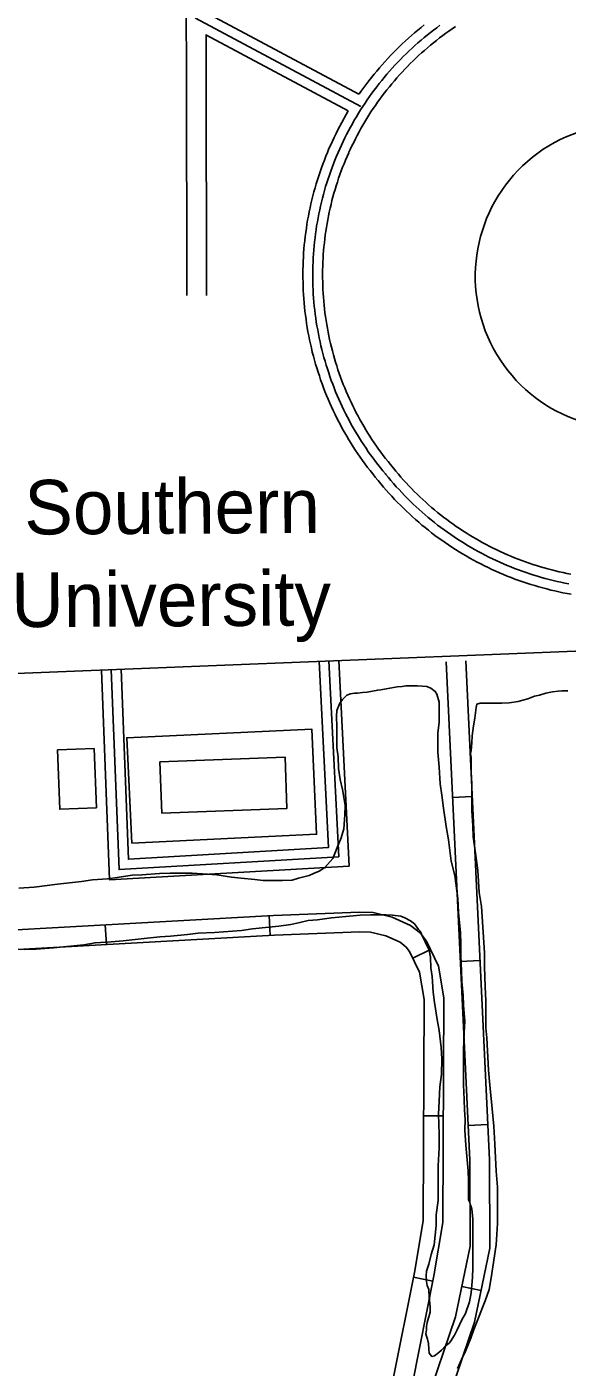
# Model space of a CAD drawing. Extents: x 3313442 to 3351311, y 721974 to 747360.
# Drawn here: x 3326444 to 3327267, y 733684 to 735725 of the extents above; entities that cross this region are included whole.
import ezdxf

# ---------------------------------------------------------------- set-up
doc = ezdxf.new("R2010")
doc.units = 0
for name, color, linetype in [('V-BLDG-IDEN', 7, 'Continuous'), ('V-BLDG-OTLN', 7, 'Continuous'), ('V-ROAD-CNTR', 7, 'Continuous'), ('V-SITE-VEGE', 7, 'Continuous')]:
    doc.layers.add(name, color=color, linetype=linetype)

msp = doc.modelspace()

# ---------------------------------------------------------------- linework, layer by layer
at = {"layer": 'V-BLDG-OTLN'}
for points in [[(3326603.5, 734482.5), (3326595.9, 734642.8), (3326877.7, 734656.1), (3326885.3, 734495.9)], [(3326490.3, 734624.2), (3326546.2, 734626.4), (3326549.7, 734536.1), (3326493.8, 734534)], [(3326649.6, 734527.8), (3326646.6, 734605.9), (3326837.1, 734613.3), (3326840.1, 734535.2)], [(3326649.6, 734527.8), (3326840.1, 734535.2), (3326837.1, 734613.3), (3326646.6, 734605.9)]]:
    msp.add_lwpolyline(points, close=True, dxfattribs=at)
at = {"layer": 'V-ROAD-CNTR'}
for p, q in [((3327092.3, 734551.7), (3327122.3, 734553.1)), ((3326812.9, 734371.9), (3326814.6, 734341.9)), ((3326563.3, 734357.8), (3326564.9, 734327.9)), ((3327058.6, 734320.2), (3327031.6, 734307.2)), ((3327104.2, 734301.9), (3327134.2, 734303.4)), ((3327078.4, 734066.9), (3327048.4, 734067.1)), ((3327116.1, 734052.2), (3327146.1, 734053.7)), ((3327062.3, 733815.5), (3327032.8, 733821.4)), ((3327106.5, 733807.4), (3327135.9, 733801.3))]:
    msp.add_line(p, q, dxfattribs=at)
for points in [[(3326952.7, 735604), (3326700.7, 735738.5), (3326692.7, 735930.9)], [(3326949.5, 735622.7), (3326715.3, 735747.7), (3326708.3, 735916.3)], [(3326686.4, 735744.1), (3326687.2, 735662.7), (3326687.3, 735316.1)], [(3326933.5, 735597.2), (3326716.6, 735713)], [(3326716.7, 735713.7), (3326717.2, 735662.9), (3326717.3, 735316.1)], [(3326920.4, 735539.4), (3326922.9, 735545), (3326925.5, 735550.6), (3326928.2, 735556.1), (3326931, 735561.5), (3326933.8, 735567), (3326936.7, 735572.4), (3326939.7, 735577.7), (3326942.7, 735583.1), (3326945.8, 735588.3), (3326949, 735593.6), (3326952.3, 735598.8), (3326955.6, 735603.9), (3326959, 735609), (3326962.4, 735614.1), (3326965.9, 735619.1), (3326969.5, 735624.1), (3326973.1, 735629), (3326976.9, 735633.9), (3326980.6, 735638.8), (3326984.5, 735643.5), (3326988.4, 735648.3), (3326992.3, 735653), (3326996.3, 735657.6), (3327000.4, 735662.2), (3327004.5, 735666.7), (3327008.7, 735671.1), (3327013, 735675.6), (3327017.3, 735679.9), (3327021.7, 735684.2), (3327026.1, 735688.5), (3327030.6, 735692.6), (3327035.1, 735696.8), (3327039.7, 735700.8), (3327044.3, 735704.8), (3327049, 735708.8), (3327053.8, 735712.7), (3327058.6, 735716.5), (3327063.4, 735720.3), (3327068.3, 735723.9), (3327073.2, 735727.6)], [(3326934, 735533.2), (3326936.5, 735538.7), (3326939.1, 735544.1), (3326941.7, 735549.4), (3326944.3, 735554.7), (3326947.1, 735560), (3326949.9, 735565.2), (3326952.8, 735570.4), (3326955.7, 735575.5), (3326958.7, 735580.6), (3326961.8, 735585.7), (3326964.9, 735590.8), (3326968.1, 735595.7), (3326971.4, 735600.7), (3326974.8, 735605.6), (3326978.2, 735610.5), (3326981.6, 735615.3), (3326985.1, 735620), (3326988.7, 735624.8), (3326992.4, 735629.5), (3326996.1, 735634.1), (3326999.9, 735638.7), (3327003.7, 735643.2), (3327007.6, 735647.7), (3327011.5, 735652.1), (3327015.5, 735656.5), (3327019.6, 735660.8), (3327023.7, 735665.1), (3327027.9, 735669.3), (3327032.1, 735673.5), (3327036.4, 735677.6), (3327040.7, 735681.6), (3327045.1, 735685.6), (3327049.6, 735689.5), (3327054.1, 735693.4), (3327058.6, 735697.2), (3327063.2, 735701), (3327067.8, 735704.7), (3327072.5, 735708.3), (3327077.3, 735711.9), (3327082, 735715.4), (3327086.9, 735718.9), (3327091.7, 735722.3), (3327096.6, 735725.6)], [(3326949.5, 735622.7), (3326965, 735643.1), (3326968.9, 735648.1), (3326972.8, 735653), (3326976.8, 735657.9), (3326980.9, 735662.7), (3326985.1, 735667.5), (3326989.3, 735672.2), (3326993.5, 735676.9), (3326997.9, 735681.5), (3327002.3, 735686), (3327006.7, 735690.5), (3327011.2, 735695), (3327015.8, 735699.4), (3327020.4, 735703.7), (3327025.1, 735707.9), (3327029.8, 735712.1), (3327034.6, 735716.3), (3327039.4, 735720.3), (3327044.3, 735724.3), (3327049.3, 735728.3)], [(3326951.2, 735624.2), (3326952.7, 735626.4)], [(3326906.7, 735545.7), (3326909.3, 735551.3), (3326912, 735557), (3326914.8, 735562.7), (3326917.6, 735568.4), (3326920.6, 735574), (3326933.2, 735597.4)], [(3326978.6, 735034.8), (3326974.6, 735039.6), (3326970.7, 735044.5), (3326966.7, 735049.5), (3326962.9, 735054.5), (3326959.1, 735059.6), (3326955.4, 735064.7), (3326951.7, 735069.8), (3326948.1, 735075.1), (3326944.6, 735080.3), (3326941.1, 735085.6), (3326937.8, 735091), (3326934.5, 735096.3), (3326931.2, 735101.8), (3326928, 735107.2), (3326924.9, 735112.8), (3326921.9, 735118.3), (3326919, 735123.9), (3326916.1, 735129.5), (3326913.3, 735135.2), (3326910.5, 735140.9), (3326907.9, 735146.6), (3326905.3, 735152.4), (3326902.8, 735158.2), (3326900.4, 735164.1), (3326898, 735169.9), (3326895.7, 735175.8), (3326893.5, 735181.8), (3326891.4, 735187.7), (3326889.4, 735193.7), (3326887.4, 735199.7), (3326885.5, 735205.8), (3326883.7, 735211.8), (3326882, 735217.9), (3326880.3, 735224), (3326878.7, 735230.1), (3326877.3, 735236.3), (3326875.8, 735242.5), (3326874.5, 735248.6), (3326873.3, 735254.8), (3326872.1, 735261.1), (3326871, 735267.3), (3326870, 735273.5), (3326869.1, 735279.8), (3326868.2, 735286.1), (3326867.5, 735292.3), (3326866.8, 735298.6), (3326866.2, 735304.9), (3326865.7, 735311.2), (3326865.3, 735317.5), (3326864.9, 735323.9), (3326864.6, 735330.2), (3326864.5, 735336.5), (3326864.4, 735342.8), (3326864.3, 735349.1), (3326864.4, 735355.5), (3326864.6, 735361.8), (3326864.8, 735368.1), (3326865.1, 735374.4), (3326865.5, 735380.7), (3326866, 735387.1), (3326866.5, 735393.4), (3326867.2, 735399.6), (3326867.9, 735405.9), (3326868.7, 735412.2), (3326869.6, 735418.5), (3326870.5, 735424.7), (3326871.6, 735431), (3326872.7, 735437.2), (3326873.9, 735443.4), (3326875.2, 735449.6), (3326876.6, 735455.7), (3326878.1, 735461.9), (3326879.6, 735468), (3326881.2, 735474.2), (3326882.9, 735480.3), (3326884.7, 735486.3), (3326886.5, 735492.4), (3326888.5, 735498.4), (3326890.5, 735504.4), (3326892.5, 735510.4), (3326894.7, 735516.3), (3326897, 735522.2), (3326899.3, 735528.1), (3326901.7, 735534), (3326904.1, 735539.8), (3326906.7, 735545.5)], [(3326990.2, 735044.4), (3326986.2, 735049.1), (3326982.4, 735053.9), (3326978.6, 735058.7), (3326974.8, 735063.6), (3326971.2, 735068.5), (3326967.5, 735073.4), (3326964, 735078.4), (3326960.5, 735083.5), (3326957.1, 735088.6), (3326953.8, 735093.7), (3326950.5, 735098.9), (3326947.3, 735104.1), (3326944.1, 735109.4), (3326941.1, 735114.7), (3326938.1, 735120), (3326935.1, 735125.4), (3326932.3, 735130.8), (3326929.5, 735136.3), (3326926.8, 735141.8), (3326924.1, 735147.3), (3326921.5, 735152.9), (3326919, 735158.5), (3326916.6, 735164.1), (3326914.2, 735169.7), (3326912, 735175.4), (3326909.8, 735181.2), (3326907.6, 735186.9), (3326905.6, 735192.7), (3326903.6, 735198.5), (3326901.7, 735204.3), (3326899.9, 735210.1), (3326898.1, 735216), (3326896.4, 735221.9), (3326894.8, 735227.8), (3326893.3, 735233.8), (3326891.9, 735239.7), (3326890.5, 735245.7), (3326889.2, 735251.7), (3326888, 735257.7), (3326886.9, 735263.7), (3326885.8, 735269.8), (3326884.8, 735275.8), (3326883.9, 735281.9), (3326883.1, 735288), (3326882.4, 735294), (3326881.7, 735300.1), (3326881.1, 735306.2), (3326880.6, 735312.3), (3326880.2, 735318.5), (3326879.9, 735324.6), (3326879.6, 735330.7), (3326879.5, 735336.8), (3326879.4, 735343), (3326879.3, 735349.1), (3326879.4, 735355.2), (3326879.5, 735361.3), (3326879.8, 735367.5), (3326880.1, 735373.6), (3326880.4, 735379.7), (3326880.9, 735385.8), (3326881.5, 735391.9), (3326882.1, 735398), (3326882.8, 735404.1), (3326883.6, 735410.2), (3326884.4, 735416.3), (3326885.3, 735422.3), (3326886.4, 735428.4), (3326887.5, 735434.4), (3326888.6, 735440.4), (3326889.9, 735446.4), (3326891.2, 735452.4), (3326892.6, 735458.4), (3326894.1, 735464.3), (3326895.7, 735470.2), (3326897.3, 735476.1), (3326899, 735482), (3326900.8, 735487.9), (3326902.7, 735493.7), (3326904.7, 735499.5), (3326906.7, 735505.3), (3326908.8, 735511.1), (3326910.9, 735516.8), (3326913.2, 735522.5), (3326915.5, 735528.2), (3326917.9, 735533.8), (3326920.4, 735539.4)], [(3327001.7, 735054), (3326997.8, 735058.7), (3326994.1, 735063.3), (3326990.4, 735067.9), (3326986.8, 735072.6), (3326983.2, 735077.4), (3326979.7, 735082.2), (3326976.3, 735087), (3326972.9, 735091.9), (3326969.6, 735096.8), (3326966.4, 735101.8), (3326963.2, 735106.8), (3326960.1, 735111.9), (3326957.1, 735117), (3326954.1, 735122.1), (3326951.2, 735127.3), (3326948.4, 735132.5), (3326945.6, 735137.7), (3326942.9, 735143), (3326940.2, 735148.3), (3326937.7, 735153.7), (3326935.2, 735159.1), (3326932.8, 735164.5), (3326930.4, 735169.9), (3326928.1, 735175.4), (3326925.9, 735180.9), (3326923.8, 735186.5), (3326921.7, 735192), (3326919.7, 735197.6), (3326917.8, 735203.2), (3326916, 735208.9), (3326914.2, 735214.5), (3326912.5, 735220.2), (3326910.9, 735225.9), (3326909.3, 735231.7), (3326907.9, 735237.4), (3326906.5, 735243.2), (3326905.1, 735249), (3326903.9, 735254.8), (3326902.7, 735260.6), (3326901.6, 735266.4), (3326900.6, 735272.2), (3326899.7, 735278.1), (3326898.8, 735284), (3326898, 735289.9), (3326897.3, 735295.7), (3326896.6, 735301.6), (3326896.1, 735307.6), (3326895.6, 735313.5), (3326895.2, 735319.4), (3326894.9, 735325.3), (3326894.6, 735331.2), (3326894.5, 735337.2), (3326894.4, 735343.1), (3326894.3, 735349), (3326894.4, 735355), (3326894.5, 735360.9), (3326894.8, 735366.8), (3326895, 735372.8), (3326895.4, 735378.7), (3326895.9, 735384.6), (3326896.4, 735390.5), (3326897, 735396.4), (3326897.7, 735402.3), (3326898.4, 735408.2), (3326899.2, 735414.1), (3326900.2, 735419.9), (3326901.1, 735425.8), (3326902.2, 735431.6), (3326903.3, 735437.4), (3326904.6, 735443.3), (3326905.8, 735449), (3326907.2, 735454.8), (3326908.6, 735460.6), (3326910.2, 735466.3), (3326911.7, 735472), (3326913.4, 735477.7), (3326915.1, 735483.4), (3326917, 735489), (3326918.8, 735494.7), (3326920.8, 735500.3), (3326922.8, 735505.9), (3326924.9, 735511.4), (3326927.1, 735516.9), (3326929.4, 735522.4), (3326931.7, 735527.9), (3326934.1, 735533.4)], [(3327089.5, 734952.3), (3327084.5, 734955.8), (3327079.5, 734959.4), (3327074.5, 734963), (3327069.6, 734966.7), (3327064.8, 734970.5), (3327060, 734974.4), (3327055.3, 734978.3), (3327050.6, 734982.2), (3327045.9, 734986.3), (3327041.3, 734990.3), (3327036.8, 734994.5), (3327032.3, 734998.7), (3327027.9, 735002.9), (3327023.5, 735007.3), (3327019.2, 735011.6), (3327015, 735016.1), (3327010.8, 735020.6), (3327006.6, 735025.1), (3327002.6, 735029.7), (3326998.5, 735034.3), (3326994.6, 735039), (3326990.7, 735043.8), (3326990.2, 735044.4)], [(3327098.1, 734964.6), (3327093.1, 734968), (3327088.3, 734971.5), (3327083.5, 734975), (3327078.8, 734978.6), (3327074.1, 734982.3), (3327069.5, 734986), (3327064.9, 734989.8), (3327060.3, 734993.6), (3327055.8, 734997.5), (3327051.4, 735001.5), (3327047, 735005.5), (3327042.7, 735009.6), (3327038.4, 735013.7), (3327034.1, 735017.9), (3327030, 735022.1), (3327025.9, 735026.4), (3327021.8, 735030.7), (3327017.8, 735035.1), (3327013.8, 735039.6), (3327009.9, 735044.1), (3327006.1, 735048.6), (3327002.3, 735053.2), (3327001.8, 735053.9)], [(3327080.9, 734940), (3327075.8, 734943.6), (3327070.6, 734947.3), (3327065.5, 734951), (3327060.5, 734954.9), (3327055.5, 734958.8), (3327050.6, 734962.7), (3327045.7, 734966.7), (3327040.8, 734970.8), (3327036, 734975), (3327031.3, 734979.2), (3327026.6, 734983.5), (3327022, 734987.8), (3327017.4, 734992.2), (3327012.9, 734996.7), (3327008.5, 735001.2), (3327004.1, 735005.7), (3326999.8, 735010.4), (3326995.5, 735015.1), (3326991.3, 735019.8), (3326987.1, 735024.6), (3326983, 735029.4), (3326979.1, 735034.3), (3326978.5, 735035)], [(3327272.4, 734891.9), (3327266.5, 734893), (3327260.7, 734894.2), (3327254.9, 734895.5), (3327249.1, 734896.9), (3327243.4, 734898.3), (3327237.6, 734899.8), (3327231.9, 734901.4), (3327226.2, 734903.1), (3327220.5, 734904.9), (3327214.8, 734906.7), (3327209.2, 734908.6), (3327203.6, 734910.5), (3327198, 734912.6), (3327192.4, 734914.7), (3327186.9, 734916.9), (3327181.4, 734919.1), (3327175.9, 734921.4), (3327170.5, 734923.8), (3327165.1, 734926.3), (3327159.7, 734928.9), (3327154.3, 734931.5), (3327149, 734934.1), (3327143.8, 734936.9), (3327138.5, 734939.7), (3327133.3, 734942.6), (3327128.2, 734945.5), (3327123, 734948.5), (3327117.9, 734951.6), (3327112.9, 734954.8), (3327107.9, 734958), (3327102.9, 734961.3), (3327097.9, 734964.7)], [(3327273, 734861.2), (3327266.8, 734862.4), (3327260.6, 734863.6), (3327254.4, 734864.9), (3327248.2, 734866.3), (3327242, 734867.7), (3327235.9, 734869.3), (3327229.8, 734870.9), (3327223.6, 734872.6), (3327217.6, 734874.4), (3327211.5, 734876.2), (3327205.5, 734878.2), (3327199.5, 734880.2), (3327193.5, 734882.3), (3327187.5, 734884.5), (3327181.6, 734886.7), (3327175.7, 734889), (3327169.8, 734891.4), (3327164, 734893.9), (3327158.2, 734896.5), (3327152.4, 734899.1), (3327146.7, 734901.8), (3327141, 734904.6), (3327135.4, 734907.4), (3327129.7, 734910.4), (3327124.1, 734913.4), (3327118.6, 734916.4), (3327113.1, 734919.6), (3327107.6, 734922.8), (3327102.2, 734926.1), (3327096.8, 734929.4), (3327091.5, 734932.9), (3327086.2, 734936.4), (3327081.1, 734939.9)], [(3327269.6, 734877.1), (3327263.6, 734878.3), (3327257.6, 734879.6), (3327251.6, 734880.9), (3327245.6, 734882.3), (3327239.6, 734883.8), (3327233.7, 734885.4), (3327227.8, 734887), (3327221.9, 734888.7), (3327216, 734890.5), (3327210.1, 734892.4), (3327204.3, 734894.4), (3327198.5, 734896.4), (3327192.8, 734898.5), (3327187, 734900.7), (3327181.3, 734902.9), (3327175.6, 734905.3), (3327170, 734907.7), (3327164.3, 734910.2), (3327158.8, 734912.7), (3327153.2, 734915.3), (3327147.7, 734918), (3327142.2, 734920.8), (3327136.7, 734923.6), (3327131.3, 734926.5), (3327126, 734929.5), (3327120.6, 734932.6), (3327115.3, 734935.7), (3327110.1, 734938.9), (3327104.9, 734942.1), (3327099.7, 734945.4), (3327094.6, 734948.8), (3327089.5, 734952.3)], [(3327445.3, 734781.4), (3325663.8, 734710.1), (3324415, 734655.9)], [(3326545.2, 732307.4), (3326605.6, 732469.9), (3326879.5, 733185.6), (3327015.5, 733520), (3327051.8, 733628.2), (3327096.7, 733760.8), (3327119.3, 733868.7), (3327118.6, 733999.4), (3327082.4, 734758.4)], [(3326919, 734760.5), (3326934.6, 734447.4), (3326569.8, 734426.2), (3326557.4, 734745.9)], [(3326904, 734759.8), (3326918.9, 734461.5), (3326584.2, 734442), (3326572.3, 734746.5)], [(3326577.6, 732308.5), (3326633.6, 732459.4), (3326907.4, 733174.5), (3327043.6, 733509.6), (3327080.2, 733618.6), (3327125.7, 733752.9), (3327149.3, 733865.7), (3327148.6, 734000.2), (3327112.4, 734759.9)], [(3326889, 734759), (3326903.2, 734475.6), (3326598.6, 734457.9), (3326587.3, 734747.1)], [(3326236.1, 734339.4), (3326819.4, 734372.2), (3326950.7, 734377.4), (3326971.3, 734376.8), (3327000.4, 734369.8), (3327028.2, 734357.1), (3327043.4, 734345.3), (3327052.5, 734332.9), (3327070.8, 734294.8), (3327079.2, 734246.9), (3327077.7, 733904.5), (3327063.8, 733823.3), (3327030.7, 733657.2)], [(3326237.8, 734309.5), (3326820.9, 734342.3), (3326950.9, 734347.4), (3326967.3, 734346.9), (3326990.6, 734341.3), (3327012.6, 734331.3), (3327021.7, 734324.1), (3327026.7, 734317.4), (3327041.9, 734285.6), (3327049.2, 734244.3), (3327047.7, 733907.1), (3327034.3, 733828.7), (3327001.5, 733664.2)]]:
    msp.add_lwpolyline(points, dxfattribs=at)
msp.add_arc((3327359.2, 735345.4), 232.2, 51.3001, 0.4553, dxfattribs=at)
at = {"layer": 'V-SITE-VEGE'}
for points in [[(3326920.5, 734695.3), (3326924.7, 734700.8), (3326931.4, 734707.5), (3326936.9, 734709.9), (3326943, 734710.5), (3326947.3, 734710.5), (3326955.2, 734711.7), (3326962.5, 734712.3), (3326978.3, 734715.3), (3326983.2, 734715.9), (3327008.1, 734720.2), (3327015.4, 734720.8), (3327021.5, 734722), (3327039.1, 734721.9), (3327053.1, 734720.7), (3327059.2, 734718.3), (3327065.9, 734713.4), (3327068.3, 734709.1), (3327072, 734697), (3327071.9, 734665.9), (3327070.1, 734650.1), (3327070.1, 734620.9), (3327071.9, 734597.8), (3327073.6, 734572.8), (3327076.1, 734555.2), (3327078.5, 734535.7), (3327082.7, 734507.7), (3327086.3, 734487.1), (3327090.5, 734454.8), (3327096, 734432.9), (3327100.2, 734398.2), (3327101.4, 734376.9), (3327104.4, 734346.5), (3327105, 734328.9), (3327105, 734310.6)], [(3327120.5, 734612.3), (3327119.9, 734619), (3327120.6, 734622.7), (3327121.8, 734635.5), (3327122.4, 734645.8), (3327124.2, 734661), (3327126.1, 734672.6), (3327128.5, 734689), (3327129.2, 734693.8), (3327134.6, 734695.7), (3327167.5, 734695.6), (3327178.4, 734696.2), (3327192.4, 734698), (3327199.7, 734699.8), (3327207, 734702.3), (3327217.4, 734705.9), (3327224.7, 734707.7), (3327234.4, 734710.8), (3327244.8, 734712.6), (3327253.3, 734713.8), (3327258.8, 734714.4), (3327267.9, 734714.4)], [(3326431.6, 734413.6), (3326454.7, 734415.4), (3326490.6, 734419.6), (3326504, 734421.4), (3326527.1, 734423.8), (3326543.6, 734426.3), (3326566.7, 734428.1), (3326581.3, 734429.9), (3326604.4, 734433.5), (3326619, 734434.1), (3326645.8, 734435.9), (3326662.2, 734436.5), (3326695.7, 734436.4), (3326718.8, 734435.2), (3326733.4, 734433.9), (3326755.3, 734430.3), (3326770.5, 734429), (3326791.2, 734427.2), (3326804, 734425.3), (3326833.2, 734425.3), (3326847.8, 734425.9), (3326857.5, 734428.9), (3326873.9, 734433.2), (3326880.6, 734436.2), (3326889.1, 734439.8), (3326897.7, 734445.3), (3326909.9, 734458.7), (3326914.1, 734469), (3326916.6, 734475.7), (3326922.7, 734490.3), (3326926.9, 734504.3), (3326928.2, 734525), (3326928.8, 734540.2), (3326924.6, 734563.9), (3326921, 734579.1), (3326918.5, 734596.2), (3326918, 734613.8), (3326916.1, 734627.2), (3326916.2, 734659.4), (3326915.6, 734675.9), (3326916.2, 734684.4), (3326920.5, 734695.3)], [(3327099.9, 733682.2), (3327106, 733696.1), (3327112.1, 733708.9), (3327120.1, 733728.4), (3327125, 733741.8), (3327132.9, 733761.8), (3327137.8, 733775.2), (3327142.1, 733785.5), (3327148.2, 733802.6), (3327151.2, 733820.2), (3327158.6, 733870.7), (3327161.1, 733902.9), (3327161.1, 733958.3), (3327158.7, 733982.6), (3327156.9, 734024), (3327155.1, 734051.4), (3327152.7, 734077.5), (3327149.1, 734114), (3327147.3, 734136.6), (3327144.4, 734185.8), (3327143.2, 734201.1), (3327143.2, 734242.4), (3327142, 734263.7), (3327140.8, 734294.7), (3327140.9, 734315.4), (3327136.7, 734386), (3327133.1, 734407.3), (3327130.7, 734440.8), (3327127.7, 734463.3), (3327124, 734491.9), (3327123.5, 734508.9), (3327121.7, 734531.4), (3327121.7, 734572.8), (3327120.5, 734590.4), (3327120.5, 734612.3)], [(3327105, 734310.6), (3327106.2, 734287.5), (3327106.7, 734271.7), (3327108.5, 734250.4), (3327109.1, 734235.8), (3327110.9, 734211.4), (3327110.3, 734193.8), (3327109, 734167.6), (3327109, 734114.1), (3327110.2, 734092.2), (3327110.8, 734075.8), (3327111.4, 734061.8), (3327111.3, 734045.3), (3327112.5, 734022.2), (3327114.3, 734005.8), (3327116.1, 733983.3), (3327116.7, 733968.1), (3327116.7, 733947.4), (3327116.7, 733939.5), (3327118.5, 733935.2), (3327119.1, 733932.8), (3327120.9, 733928.5), (3327121.5, 733924.9), (3327123.3, 733910.3), (3327123.2, 733835.4), (3327122.6, 733820.8), (3327120.8, 733797.7), (3327118.3, 733783.7), (3327112.2, 733766.1), (3327106.7, 733756.4), (3327099.4, 733741.2), (3327095.1, 733733.3), (3327089, 733723.5), (3327087.2, 733721.1), (3327085.4, 733719.3), (3327081.7, 733716.9), (3327075.6, 733710.2), (3327071.4, 733706.5), (3327064.7, 733701.7), (3327061, 733700.5), (3327056.8, 733705.9), (3327056.2, 733712), (3327055.6, 733720.5), (3327054.4, 733727.2), (3327052.6, 733731.5), (3327051.9, 733735.1), (3327052.6, 733741.2), (3327052.6, 733746.1), (3327053.8, 733752.2), (3327058.1, 733768), (3327058.1, 733776.5), (3327056.9, 733791.1), (3327056.3, 733802.7), (3327053.9, 733808.8), (3327052.7, 733814.8), (3327052.1, 733823.4), (3327052.7, 733830.7), (3327056.3, 733841), (3327060, 733856.2), (3327064.3, 733870.8), (3327067.4, 733900), (3327067.4, 733916.4), (3327070.4, 733938.3), (3327070.5, 733952.9), (3327070.5, 733991.2), (3327071.8, 734018.6), (3327071.8, 734039.3), (3327071.2, 734069.7), (3327071.8, 734089.2), (3327073.1, 734111.1), (3327075.5, 734130), (3327076.2, 734153.7), (3327075, 734171.3), (3327072, 734196.9), (3327069, 734213.9), (3327064.7, 734239.5), (3327062.9, 734255.3), (3327061.1, 734279), (3327059.3, 734292.4), (3327058.7, 734308.8), (3327056.9, 734319.2), (3327050.8, 734332), (3327047.2, 734339.3), (3327043, 734348.4), (3327040.5, 734350.8), (3327034.5, 734359.4), (3327028.4, 734364.2), (3327019.9, 734368.5), (3327013.8, 734370.9), (3327001, 734372.8), (3326991.3, 734373.4), (3326967.5, 734373.4), (3326951.7, 734372.8), (3326940.8, 734371.6), (3326907.9, 734368.6), (3326886.6, 734365.6), (3326872.6, 734364.4), (3326859.9, 734361.4), (3326845.9, 734358.4), (3326827.6, 734356), (3326812.4, 734354.2)], [(3326812.4, 734354.2), (3326787.4, 734351.7), (3326771, 734349.3), (3326729.6, 734346.3), (3326704.7, 734345.2), (3326688.3, 734343.3), (3326662.7, 734340.9), (3326646.3, 734339.7), (3326622.6, 734337.3), (3326590.3, 734333.7), (3326572.1, 734331.9), (3326547.7, 734330.7), (3326530.7, 734327.7), (3326484.4, 734322.9), (3326457.7, 734321.1), (3326439.4, 734320.5)]]:
    msp.add_lwpolyline(points, dxfattribs=at)

# ---------------------------------------------------------------- texts
at = {"layer": 'V-BLDG-IDEN'}
for s, p in [('Southern', (3326440, 734952.2)), ('University', (3326420.1, 734811.1))]:
    msp.add_text(s, height=83, rotation=0.3179, dxfattribs=at).set_placement(p)

doc.saveas('drawing.dxf')
